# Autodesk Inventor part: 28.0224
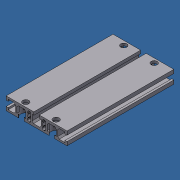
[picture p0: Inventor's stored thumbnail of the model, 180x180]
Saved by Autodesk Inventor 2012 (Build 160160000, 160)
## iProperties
Created: 2007-06
Part Number: 28.0224
Material: Aluminum-6061
Document SubType Name: Modeling
Designer: Andy Moles
Density: 2.71 g/cm^3
Description: L = 6.220", MACHINE TO 28.0224
Stock Number: 20.0995 PROFILE 90X19
Mass: 307.269 g
Surface Area: 766.901 cm^2
Volume: 113.383 cm^3
Vendor: F
Author: Andy Moles
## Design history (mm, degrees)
sketch "Sketch1"
  geometry: L1 (18.4, -9.5)-(18.4, -5) reference; L2 (17.9, -5)-(15.7, -5) reference; L3 (15.7, -5)-(15.7, 3.5) reference; L4 (15.7, 3.5)-(18, 5.8) reference; L5 (18, 5.8)-(27, 5.8) reference; L6 (27, 5.8)-(29.3, 3.5) reference; L7 (29.3, 3.5)-(29.3, -5) reference; L8 (26.6, -5)-(26.6, -9.5) reference; L9 (45, -9.5)-(26.9, -9.5) reference; L10 (45, -4.1)-(45, -9.5) reference; L11 (45, -4.1)-(42, -4.1) reference; L12 (42, -4.6)-(42, -6.8) reference; L13 (42, -6.8)-(33.5, -6.8) reference; L14 (33.5, -6.8)-(31.2, -4.5) reference; L15 (31.2, -4.5)-(31.2, 4.5) reference; L16 (31.2, 4.5)-(33.5, 6.8) reference; L17 (33.5, 6.8)-(42, 6.8) reference; L18 (42, 4.1)-(45, 4.1) reference; L19 (45, 9.5)-(45, 4.1) reference; L20 (4.4, 9.5)-(45, 9.5) reference; L21 (4.1, 9.5)-(4.1, 5) reference; L22 (4.6, 5)-(6.8, 5) reference; L23 (6.8, 5)-(6.8, -3.5) reference; L24 (6.8, -3.5)-(4.5, -5.8) reference; L25 (4.5, -5.8)-(-4.5, -5.8) reference; L26 (-4.5, -5.8)-(-6.8, -3.5) reference; L27 (-6.8, -3.5)-(-6.8, 5) reference; L28 (-4.1, 5)-(-4.1, 9.5) reference; L29 (-45, 4.1)-(-45, 9.5) reference; L30 (-45, 4.1)-(-42, 4.1) reference; L31 (-42, 4.1)-(-42, 6.8) reference; L32 (-42, 6.8)-(-33.5, 6.8) reference; L33 (-33.5, 6.8)-(-31.2, 4.5) reference; L34 (-31.2, 4.5)-(-31.2, -4.5) reference; L35 (-31.2, -4.5)-(-33.5, -6.8) reference; L36 (-33.5, -6.8)-(-42, -6.8) reference; L37 (-42, -6.8)-(-42, -4.1) reference; L38 (-42, -4.1)-(-45, -4.1) reference; L39 (-45, -9.5)-(-45, -4.1) reference; L40 (-26.6, -9.5)-(-26.6, -5) reference; L41 (-29.3, -5)-(-29.3, 3.5) reference; L42 (-29.3, 3.5)-(-27, 5.8) reference; L43 (-27, 5.8)-(-18, 5.8) reference; L44 (-18, 5.8)-(-15.7, 3.5) reference; L45 (-15.7, 3.5)-(-15.7, -5) reference; L46 (-15.7, -5)-(-17.9, -5) reference; L47 (-18.4, -5)-(-18.4, -9.5) reference; L48 (-18.1, -9.5)-(-18.4, -9.5) reference; L49 (-26.6, -9.5)-(-45, -9.5) reference; L50 (-17.9, -5)-(-18.4, -5) reference; L51 (-26.6, -5)-(-29.3, -5) reference; L52 (-6.8, 5)-(-4.1, 5) reference; L53 (4.1, 5)-(4.6, 5) reference; L54 (-45, 9.5)-(-4.1, 9.5) reference; L55 (4.1, 9.5)-(4.4, 9.5) reference; L56 (29.3, -5)-(26.6, -5) reference; L57 (18.4, -5)-(17.9, -5) reference; L58 (26.9, -9.5)-(26.6, -9.5) reference; L59 (18.4, -9.5)-(-18.1, -9.5) reference; L60 (42, 6.8)-(42, 4.1) reference; L61 (42, -4.1)-(42, -4.6) reference; L62 (-9.354, -2.59)-(-8.993, -2.95); L63 (-10.7, -7)-(-11.3, -7); L64 (-8.7, -3.657)-(-8.7, -5)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; A1 r 2.5 centre (-11, 0) between (-9.333, -1.863) and (-9.333, 1.863); A2 r 1 centre (-9.7, -3.657) between (-8.7, -3.657) and (-8.993, -2.95); A3 r 2 centre (-10.7, -5) between (-10.7, -7) and (-8.7, -5); A4 r 0.5 centre (-9, -2.236) between (-9.333, -1.863) and (-9.354, -2.59); A5 r 1 centre (-12.3, -3.657) between (-13.007, -2.95) and (-13.3, -3.657); A6 r 2.5 centre (-11, 0) between (-12.667, 1.863) and (-12.667, -1.863); A7 r 2 centre (-11.3, -5) between (-13.3, -5) and (-11.3, -7); A8 r 0.5 centre (-13, -2.236) between (-12.646, -2.59) and (-12.667, -1.863); A9 r 0.5 centre (-13, 2.236) between (-12.667, 1.863) and (-12.646, 2.59); A10 r 2 centre (-11.3, 5) between (-11.3, 7) and (-13.3, 5); A11 r 0.5 centre (-9, 2.236) between (-9.354, 2.59) and (-9.333, 1.863); A12 r 1 centre (-9.7, 3.657) between (-8.993, 2.95) and (-8.7, 3.657); A13 r 2 centre (-10.7, 5) between (-8.7, 5) and (-10.7, 7); A14 r 1 centre (-12.3, 3.657) between (-13.3, 3.657) and (-13.007, 2.95); A15 r 1 centre (12.3, 3.657) between (13.007, 2.95) and (13.3, 3.657); A16 r 0.5 centre (13, 2.236) between (12.646, 2.59) and (12.667, 1.863); A17 r 2 centre (11.3, 5) between (13.3, 5) and (11.3, 7); A18 r 0.5 centre (9, 2.236) between (9.333, 1.863) and (9.354, 2.59); A19 r 1 centre (9.7, 3.657) between (8.7, 3.657) and (8.993, 2.95); A20 r 2 centre (10.7, 5) between (10.7, 7) and (8.7, 5); A21 r 1 centre (9.7, -3.657) between (8.993, -2.95) and (8.7, -3.657); A22 r 2.5 centre (11, 0) between (9.333, 1.863) and (9.333, -1.863); A23 r 0.5 centre (9, -2.236) between (9.354, -2.59) and (9.333, -1.863); A24 r 2 centre (10.7, -5) between (8.7, -5) and (10.7, -7); A25 r 2.5 centre (11, 0) between (12.667, -1.863) and (12.667, 1.863); A26 r 0.5 centre (13, -2.236) between (12.667, -1.863) and (12.646, -2.59); A27 r 1 centre (12.3, -3.657) between (13.3, -3.657) and (13.007, -2.95); A28 r 2 centre (11.3, -5) between (11.3, -7) and (13.3, -5)
  constraints: 162 end point, 56 point on circle, 28 centre point, 28 horizontal, 23 vertical, 71 other
extrude "Extrusion1" new body sketch "Sketch1" stored distance "d0" = 158; taper "d1" = 0 deg
sketch "Sketch2"
  geometry: L1 (0, -158)-(36.8, -158) reference; L2 (63.4, -158)-(63.4, 0) reference; L3 (36.8, 0)-(0, 0) reference; 5 further points
  constraints: 2 horizontal alignment, 2 vertical alignment
  dimensions: "d2" = 158 distance of L1.end L3.start (derived); "d5" = 22.5 distance from line of point (40.9, -6.5) L2; "d6" = 67.5 distance from line of point (-4.1, -6.5) L2; "d14" = 6.5 distance from line of point (40.9, -6.5) L3; "d15" = 6.5 distance from line of point (40.9, -151.5) L1
hole "Hole1" sketch "Sketch2" at (40.9, -6.5), (-4.1, -6.5), (-4.1, -151.5), (40.9, -151.5) diameter "d7" = 9; stored, may be unused: countersink angle "d11" = 90 deg, drill point angle "d13" = 118 deg; dims "d8" = 6, "d9" = 15, "d10" = 15.3, "d12" = 8
body "Solid1"
